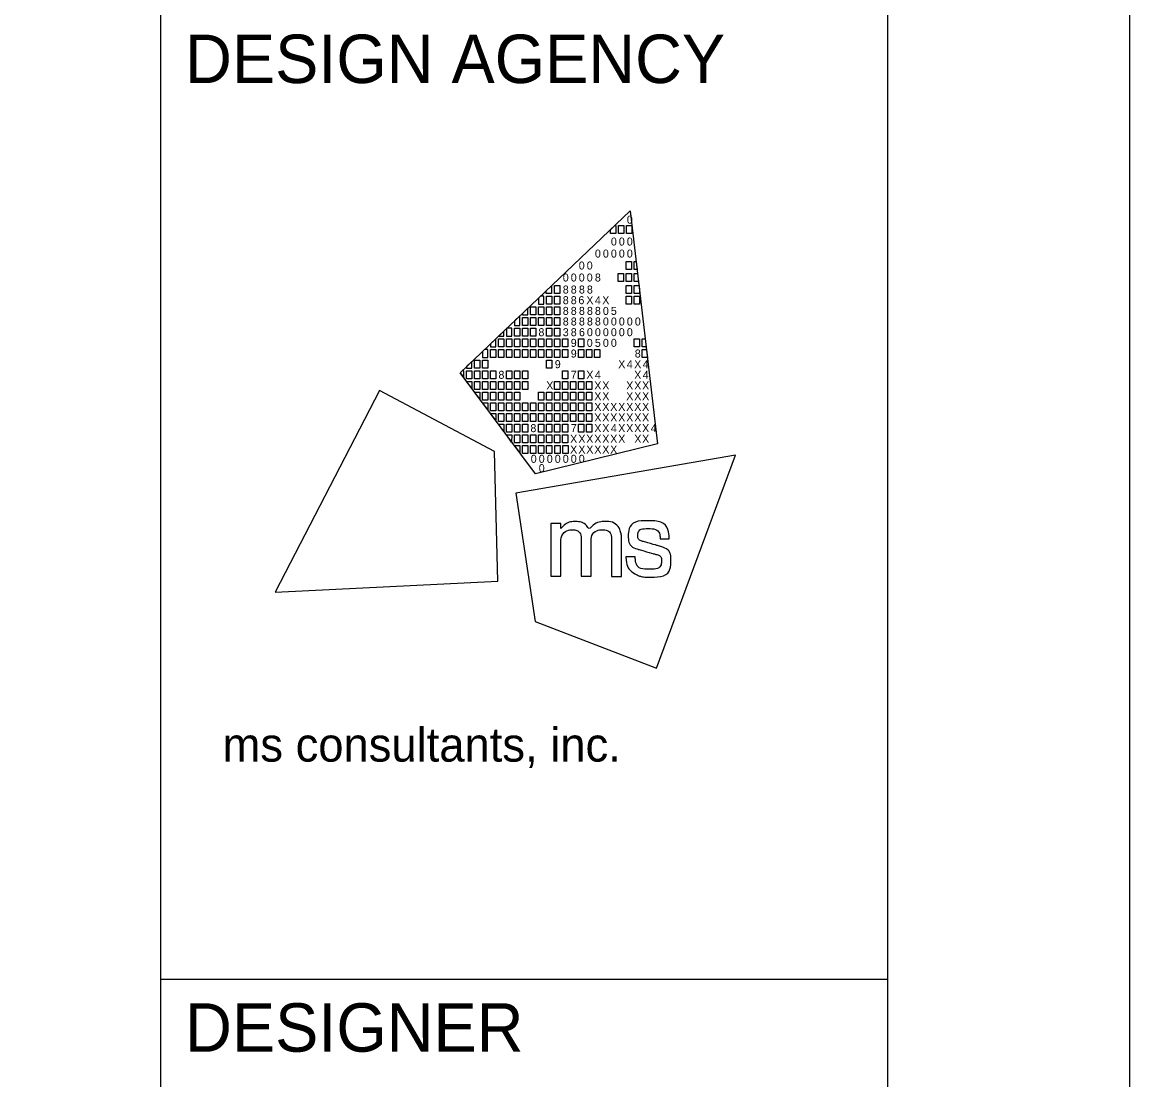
# Model space of a CAD drawing. Extents: x -2.6 to 34, y 0 to 22.
# Drawn here: x 31.714 to 34, y 2.292 to 4.476 of the extents above; entities that cross this region are included whole.
import ezdxf

# ---------------------------------------------------------------- set-up
doc = ezdxf.new("R2010")
doc.units = 0
for name, color, linetype in [('Default', 7, 'Continuous'), ('SH_Border', 7, 'Continuous'), ('SH_Cut_Line', 7, 'Continuous'), ('SH_Data', 7, 'Continuous')]:
    doc.layers.add(name, color=color, linetype=linetype)

msp = doc.modelspace()

# ---------------------------------------------------------------- linework, layer by layer
at = {"layer": 'Default'}
for p, q in [((32.6175, 3.7519), (32.9688, 4.0861)), ((32.9688, 4.0861), (32.9688, 4.0861)), ((32.9688, 4.0861), (33.0253, 3.6052)), ((32.773, 3.543), (32.6175, 3.7519)), ((33.0253, 3.6052), (32.773, 3.543))]:
    msp.add_line(p, q, dxfattribs=at)
for points in [[(32.9279, 4.0472), (32.9369, 4.0558), (32.9389, 4.0558), (32.9389, 4.0393), (32.9279, 4.0393)], [(32.9444, 4.0558), (32.9554, 4.0558), (32.9554, 4.0393), (32.9444, 4.0393)], [(32.9609, 4.0558), (32.9719, 4.0558), (32.9719, 4.0393), (32.9609, 4.0393)], [(32.9606, 3.9815), (32.9716, 3.9815), (32.9716, 3.965), (32.9606, 3.965)], [(32.9771, 3.9815), (32.9811, 3.9815), (32.983, 3.965), (32.9771, 3.965)], [(32.9441, 3.9567), (32.9551, 3.9567), (32.9551, 3.9402), (32.9441, 3.9402)], [(32.9606, 3.9567), (32.9716, 3.9567), (32.9716, 3.9402), (32.9606, 3.9402)], [(32.9771, 3.9567), (32.984, 3.9567), (32.9859, 3.9402), (32.9771, 3.9402)], [(32.7953, 3.9211), (32.8064, 3.9316), (32.8064, 3.9154), (32.7953, 3.9154)], [(32.7958, 3.9099), (32.8068, 3.9099), (32.8068, 3.8934), (32.7958, 3.8934)], [(32.8123, 3.9319), (32.8233, 3.9319), (32.8233, 3.9154), (32.8123, 3.9154)], [(32.8123, 3.9099), (32.8233, 3.9099), (32.8233, 3.8934), (32.8123, 3.8934)], [(32.9606, 3.9319), (32.9716, 3.9319), (32.9716, 3.9154), (32.9606, 3.9154)], [(32.9606, 3.9099), (32.9716, 3.9099), (32.9716, 3.8934), (32.9606, 3.8934)], [(32.9771, 3.9319), (32.9869, 3.9319), (32.9881, 3.9218), (32.9881, 3.9154), (32.9771, 3.9154)], [(32.9771, 3.9099), (32.9881, 3.9099), (32.9881, 3.8934), (32.9771, 3.8934)], [(32.7627, 3.8879), (32.7737, 3.8879), (32.7737, 3.8714), (32.7627, 3.8714)], [(32.7793, 3.8879), (32.7903, 3.8879), (32.7903, 3.8714), (32.7793, 3.8714)], [(32.7958, 3.8879), (32.8068, 3.8879), (32.8068, 3.8714), (32.7958, 3.8714)], [(32.8123, 3.8879), (32.8233, 3.8879), (32.8233, 3.8714), (32.8123, 3.8714)], [(32.7462, 3.8659), (32.7572, 3.8659), (32.7572, 3.8494), (32.7462, 3.8494)], [(32.7627, 3.8659), (32.7737, 3.8659), (32.7737, 3.8494), (32.7627, 3.8494)], [(32.7793, 3.8659), (32.7903, 3.8659), (32.7903, 3.8494), (32.7793, 3.8494)], [(32.7958, 3.8659), (32.8068, 3.8659), (32.8068, 3.8494), (32.7958, 3.8494)], [(32.8123, 3.8659), (32.8233, 3.8659), (32.8233, 3.8494), (32.8123, 3.8494)], [(32.7297, 3.8439), (32.7407, 3.8439), (32.7407, 3.8273), (32.7297, 3.8273)], [(32.7462, 3.8439), (32.7572, 3.8439), (32.7572, 3.8273), (32.7462, 3.8273)], [(32.7627, 3.8439), (32.7737, 3.8439), (32.7737, 3.8273), (32.7627, 3.8273)], [(32.7958, 3.8439), (32.8068, 3.8439), (32.8068, 3.8273), (32.7958, 3.8273)], [(32.8123, 3.8439), (32.8233, 3.8439), (32.8233, 3.8273), (32.8123, 3.8273)], [(32.6967, 3.8218), (32.7077, 3.8218), (32.7077, 3.8053), (32.6967, 3.8053)], [(32.7132, 3.8218), (32.7242, 3.8218), (32.7242, 3.8053), (32.7132, 3.8053)], [(32.7297, 3.8218), (32.7407, 3.8218), (32.7407, 3.8053), (32.7297, 3.8053)], [(32.7462, 3.8218), (32.7572, 3.8218), (32.7572, 3.8053), (32.7462, 3.8053)], [(32.7627, 3.8218), (32.7737, 3.8218), (32.7737, 3.8053), (32.7627, 3.8053)], [(32.7793, 3.8218), (32.7903, 3.8218), (32.7903, 3.8053), (32.7793, 3.8053)], [(32.7958, 3.8218), (32.8068, 3.8218), (32.8068, 3.8053), (32.7958, 3.8053)], [(32.8123, 3.8218), (32.8233, 3.8218), (32.8233, 3.8053), (32.8123, 3.8053)], [(32.8288, 3.8218), (32.8398, 3.8218), (32.8398, 3.8053), (32.8288, 3.8053)], [(32.8618, 3.8218), (32.8728, 3.8218), (32.8728, 3.8053), (32.8618, 3.8053)], [(32.9771, 3.8218), (32.9881, 3.8218), (32.9881, 3.8053), (32.9771, 3.8053)], [(32.9935, 3.8218), (32.9998, 3.8218), (33.0018, 3.8053), (32.9935, 3.8053)], [(32.6802, 3.7998), (32.6912, 3.7998), (32.6912, 3.7833), (32.6802, 3.7833)], [(32.6967, 3.7998), (32.7077, 3.7998), (32.7077, 3.7833), (32.6967, 3.7833)], [(32.7132, 3.7998), (32.7242, 3.7998), (32.7242, 3.7833), (32.7132, 3.7833)], [(32.7297, 3.7998), (32.7407, 3.7998), (32.7407, 3.7833), (32.7297, 3.7833)], [(32.7462, 3.7998), (32.7572, 3.7998), (32.7572, 3.7833), (32.7462, 3.7833)], [(32.7627, 3.7998), (32.7737, 3.7998), (32.7737, 3.7833), (32.7627, 3.7833)], [(32.7793, 3.7998), (32.7903, 3.7998), (32.7903, 3.7833), (32.7793, 3.7833)], [(32.7958, 3.7998), (32.8068, 3.7998), (32.8068, 3.7833), (32.7958, 3.7833)], [(32.8123, 3.7998), (32.8233, 3.7998), (32.8233, 3.7833), (32.8123, 3.7833)], [(32.8288, 3.7998), (32.8398, 3.7998), (32.8398, 3.7833), (32.8288, 3.7833)], [(32.8618, 3.7998), (32.8728, 3.7998), (32.8728, 3.7833), (32.8618, 3.7833)], [(32.8783, 3.7998), (32.8893, 3.7998), (32.8893, 3.7833), (32.8783, 3.7833)], [(32.8947, 3.7998), (32.9057, 3.7998), (32.9057, 3.7833), (32.8947, 3.7833)], [(32.9935, 3.7998), (33.0024, 3.7998), (33.0044, 3.7833), (32.9935, 3.7833)], [(32.6471, 3.7778), (32.6581, 3.7778), (32.6581, 3.7613), (32.6471, 3.7613)], [(32.6637, 3.7778), (32.6747, 3.7778), (32.6747, 3.7613), (32.6637, 3.7613)], [(32.7958, 3.7778), (32.8068, 3.7778), (32.8068, 3.7613), (32.7958, 3.7613)], [(32.6306, 3.7558), (32.6416, 3.7558), (32.6416, 3.7393), (32.6306, 3.7393)], [(32.6471, 3.7558), (32.6581, 3.7558), (32.6581, 3.7393), (32.6471, 3.7393)], [(32.6637, 3.7558), (32.6747, 3.7558), (32.6747, 3.7393), (32.6637, 3.7393)], [(32.6802, 3.7558), (32.6912, 3.7558), (32.6912, 3.7393), (32.6802, 3.7393)], [(32.7132, 3.7558), (32.7242, 3.7558), (32.7242, 3.7393), (32.7132, 3.7393)], [(32.7297, 3.7558), (32.7407, 3.7558), (32.7407, 3.7393), (32.7297, 3.7393)], [(32.7462, 3.7558), (32.7572, 3.7558), (32.7572, 3.7393), (32.7462, 3.7393)], [(32.8288, 3.7558), (32.8398, 3.7558), (32.8398, 3.7393), (32.8288, 3.7393)], [(32.8618, 3.7558), (32.8728, 3.7558), (32.8728, 3.7393), (32.8618, 3.7393)], [(32.6306, 3.7338), (32.6416, 3.7338), (32.6416, 3.72)], [(32.6471, 3.7338), (32.6581, 3.7338), (32.6581, 3.7173), (32.6471, 3.7173)], [(32.6637, 3.7338), (32.6747, 3.7338), (32.6747, 3.7173), (32.6637, 3.7173)], [(32.6802, 3.7338), (32.6912, 3.7338), (32.6912, 3.7173), (32.6802, 3.7173)], [(32.6967, 3.7338), (32.7077, 3.7338), (32.7077, 3.7173), (32.6967, 3.7173)], [(32.7132, 3.7338), (32.7242, 3.7338), (32.7242, 3.7173), (32.7132, 3.7173)], [(32.7297, 3.7338), (32.7407, 3.7338), (32.7407, 3.7173), (32.7297, 3.7173)], [(32.7462, 3.7338), (32.7572, 3.7338), (32.7572, 3.7173), (32.7462, 3.7173)], [(32.8123, 3.7338), (32.8233, 3.7338), (32.8233, 3.7173), (32.8123, 3.7173)], [(32.8288, 3.7338), (32.8398, 3.7338), (32.8398, 3.7173), (32.8288, 3.7173)], [(32.8453, 3.7338), (32.8563, 3.7338), (32.8563, 3.7173), (32.8453, 3.7173)], [(32.8618, 3.7338), (32.8728, 3.7338), (32.8728, 3.7173), (32.8618, 3.7173)], [(32.8783, 3.7338), (32.8893, 3.7338), (32.8893, 3.7173), (32.8783, 3.7173)], [(32.6471, 3.7117), (32.6581, 3.7117), (32.6581, 3.698)], [(32.6637, 3.7117), (32.6747, 3.7117), (32.6747, 3.6952), (32.6637, 3.6952)], [(32.6802, 3.7117), (32.6912, 3.7117), (32.6912, 3.6952), (32.6802, 3.6952)], [(32.6967, 3.7117), (32.7077, 3.7117), (32.7077, 3.6952), (32.6967, 3.6952)], [(32.7132, 3.7117), (32.7242, 3.7117), (32.7242, 3.6952), (32.7132, 3.6952)], [(32.7297, 3.7117), (32.7407, 3.7117), (32.7407, 3.6952), (32.7297, 3.6952)], [(32.7793, 3.7117), (32.7903, 3.7117), (32.7903, 3.6952), (32.7793, 3.6952)], [(32.7958, 3.7117), (32.8068, 3.7117), (32.8068, 3.6952), (32.7958, 3.6952)], [(32.8123, 3.7117), (32.8233, 3.7117), (32.8233, 3.6952), (32.8123, 3.6952)], [(32.8288, 3.7117), (32.8398, 3.7117), (32.8398, 3.6952), (32.8288, 3.6952)], [(32.8453, 3.7117), (32.8563, 3.7117), (32.8563, 3.6952), (32.8453, 3.6952)], [(32.8618, 3.7117), (32.8728, 3.7117), (32.8728, 3.6952), (32.8618, 3.6952)], [(32.8783, 3.7117), (32.8893, 3.7117), (32.8893, 3.6952), (32.8783, 3.6952)], [(32.6637, 3.6897), (32.6747, 3.6897), (32.6747, 3.676)], [(32.6747, 3.6897), (32.6747, 3.6897), (32.6747, 3.6897)], [(32.6802, 3.6897), (32.6912, 3.6897), (32.6912, 3.6732), (32.6802, 3.6732)], [(32.6967, 3.6897), (32.7077, 3.6897), (32.7077, 3.6732), (32.6967, 3.6732)], [(32.7132, 3.6897), (32.7242, 3.6897), (32.7242, 3.6732), (32.7132, 3.6732)], [(32.7297, 3.6897), (32.7407, 3.6897), (32.7407, 3.6732), (32.7297, 3.6732)], [(32.7462, 3.6897), (32.7572, 3.6897), (32.7572, 3.6732), (32.7462, 3.6732)], [(32.7627, 3.6897), (32.7737, 3.6897), (32.7737, 3.6732), (32.7627, 3.6732)], [(32.7793, 3.6897), (32.7903, 3.6897), (32.7903, 3.6732), (32.7793, 3.6732)], [(32.7958, 3.6897), (32.8068, 3.6897), (32.8068, 3.6732), (32.7958, 3.6732)], [(32.8123, 3.6897), (32.8233, 3.6897), (32.8233, 3.6732), (32.8123, 3.6732)], [(32.8288, 3.6897), (32.8398, 3.6897), (32.8398, 3.6732), (32.8288, 3.6732)], [(32.8453, 3.6897), (32.8563, 3.6897), (32.8563, 3.6732), (32.8453, 3.6732)], [(32.8618, 3.6897), (32.8728, 3.6897), (32.8728, 3.6732), (32.8618, 3.6732)], [(32.8783, 3.6897), (32.8893, 3.6897), (32.8893, 3.6732), (32.8783, 3.6732)], [(32.6802, 3.6677), (32.6912, 3.6677), (32.6912, 3.654)], [(32.6967, 3.6677), (32.7077, 3.6677), (32.7077, 3.6512), (32.6967, 3.6512)], [(32.7132, 3.6677), (32.7242, 3.6677), (32.7242, 3.6512), (32.7132, 3.6512)], [(32.7297, 3.6677), (32.7407, 3.6677), (32.7407, 3.6512), (32.7297, 3.6512)], [(32.7462, 3.6677), (32.7572, 3.6677), (32.7572, 3.6512), (32.7462, 3.6512)], [(32.7627, 3.6677), (32.7737, 3.6677), (32.7737, 3.6512), (32.7627, 3.6512)], [(32.7793, 3.6677), (32.7903, 3.6677), (32.7903, 3.6512), (32.7793, 3.6512)], [(32.7958, 3.6677), (32.8068, 3.6677), (32.8068, 3.6512), (32.7958, 3.6512)], [(32.8123, 3.6677), (32.8233, 3.6677), (32.8233, 3.6512), (32.8123, 3.6512)], [(32.8288, 3.6677), (32.8398, 3.6677), (32.8398, 3.6512), (32.8288, 3.6512)], [(32.8453, 3.6677), (32.8563, 3.6677), (32.8563, 3.6512), (32.8453, 3.6512)], [(32.8618, 3.6677), (32.8728, 3.6677), (32.8728, 3.6512), (32.8618, 3.6512)], [(32.8783, 3.6677), (32.8893, 3.6677), (32.8893, 3.6512), (32.8783, 3.6512)], [(32.7077, 3.6305), (32.6965, 3.6457), (32.7077, 3.6457)], [(32.7132, 3.6457), (32.7242, 3.6457), (32.7242, 3.6292), (32.7132, 3.6292)], [(32.7297, 3.6457), (32.7407, 3.6457), (32.7407, 3.6292), (32.7297, 3.6292)], [(32.7462, 3.6457), (32.7572, 3.6457), (32.7572, 3.6292), (32.7462, 3.6292)], [(32.7793, 3.6457), (32.7903, 3.6457), (32.7903, 3.6292), (32.7793, 3.6292)], [(32.7958, 3.6457), (32.8068, 3.6457), (32.8068, 3.6292), (32.7958, 3.6292)], [(32.8123, 3.6457), (32.8233, 3.6457), (32.8233, 3.6292), (32.8123, 3.6292)], [(32.8288, 3.6457), (32.8398, 3.6457), (32.8398, 3.6292), (32.8288, 3.6292)], [(32.8618, 3.6457), (32.8728, 3.6457), (32.8728, 3.6292), (32.8618, 3.6292)], [(32.8783, 3.6457), (32.8893, 3.6457), (32.8893, 3.6292), (32.8783, 3.6292)], [(32.724, 3.6082), (32.7132, 3.6237), (32.7242, 3.6237)], [(32.7297, 3.6237), (32.7407, 3.6237), (32.7407, 3.6072), (32.7297, 3.6072)], [(32.7462, 3.6237), (32.7572, 3.6237), (32.7572, 3.6072), (32.7462, 3.6072)], [(32.7627, 3.6237), (32.7737, 3.6237), (32.7737, 3.6072), (32.7627, 3.6072)], [(32.7793, 3.6237), (32.7903, 3.6237), (32.7903, 3.6072), (32.7793, 3.6072)], [(32.7958, 3.6237), (32.8068, 3.6237), (32.8068, 3.6072), (32.7958, 3.6072)], [(32.8123, 3.6237), (32.8233, 3.6237), (32.8233, 3.6072), (32.8123, 3.6072)], [(32.8288, 3.6237), (32.8398, 3.6237), (32.8398, 3.6072), (32.8288, 3.6072)], [(32.7302, 3.6017), (32.7407, 3.6017), (32.7408, 3.5875)], [(32.7463, 3.6017), (32.7573, 3.6017), (32.7573, 3.5852), (32.7463, 3.5852)], [(32.763, 3.6017), (32.774, 3.6017), (32.774, 3.5852), (32.763, 3.5852)], [(32.7794, 3.6017), (32.7904, 3.6017), (32.7904, 3.5852), (32.7794, 3.5852)], [(32.796, 3.6017), (32.807, 3.6017), (32.807, 3.5852), (32.796, 3.5852)], [(32.8129, 3.6017), (32.8239, 3.6017), (32.8239, 3.5851), (32.8129, 3.5851)], [(32.8296, 3.6017), (32.8406, 3.6017), (32.8406, 3.5851), (32.8296, 3.5851)]]:
    msp.add_lwpolyline(points, close=True, dxfattribs=at)
for points in [[(32.7903, 3.9099), (32.7836, 3.9099), (32.7793, 3.9058), (32.7793, 3.8934), (32.7903, 3.8934), (32.7903, 3.9099)], [(32.7407, 3.8691), (32.7297, 3.8587), (32.7297, 3.8494), (32.7407, 3.8494), (32.7407, 3.8691)], [(32.7572, 3.8849), (32.7462, 3.8744), (32.7462, 3.8714), (32.7572, 3.8714), (32.7572, 3.8849)], [(32.7242, 3.8439), (32.7141, 3.8439), (32.7132, 3.843), (32.7132, 3.8273), (32.7242, 3.8273), (32.7242, 3.8439)], [(32.6912, 3.822), (32.6802, 3.8115), (32.6802, 3.8053), (32.6912, 3.8053), (32.6912, 3.822)], [(32.7077, 3.8377), (32.6968, 3.8273), (32.7077, 3.8273), (32.7077, 3.8377)], [(32.6747, 3.7998), (32.6679, 3.7998), (32.6637, 3.7958), (32.6637, 3.7833), (32.6747, 3.7833), (32.6747, 3.7998)], [(32.6416, 3.7749), (32.6306, 3.7644), (32.6306, 3.7613), (32.6416, 3.7613), (32.6416, 3.7749)], [(32.6251, 3.7558), (32.6216, 3.7558), (32.6175, 3.7519), (32.6251, 3.7417), (32.6251, 3.7558)], [(32.4512, 3.7149), (32.2359, 3.2988), (32.6956, 3.3215), (32.6884, 3.5892), (32.4512, 3.7149)], [(33.0229, 3.1422), (33.1859, 3.5814), (32.7324, 3.5029), (32.7722, 3.2381), (33.0229, 3.1422)]]:
    msp.add_lwpolyline(points, dxfattribs=at)
for points in [[(32.8048, 3.3315), (32.8048, 3.3315), (32.8048, 3.4409), (32.8048, 3.4409), (32.8048, 3.4409), (32.8255, 3.4409), (32.8255, 3.4409), (32.8255, 3.4409), (32.8255, 3.4297), (32.8255, 3.4297), (32.8346, 3.4399), (32.8457, 3.4445), (32.8555, 3.4445), (32.8688, 3.4445), (32.8791, 3.4372), (32.8837, 3.4266), (32.8915, 3.4381), (32.905, 3.4446), (32.9166, 3.4446), (32.9325, 3.4446), (32.9451, 3.435), (32.9494, 3.4213), (32.9494, 3.4212), (32.9494, 3.4212), (32.9494, 3.4212), (32.9501, 3.419), (32.9506, 3.4172), (32.9506, 3.4071), (32.9506, 3.4071), (32.9506, 3.3314), (32.9506, 3.3314), (32.9506, 3.3314), (32.9303, 3.3314), (32.9303, 3.3314), (32.9303, 3.3314), (32.9303, 3.4048), (32.9303, 3.4048), (32.9303, 3.4201), (32.9219, 3.4274), (32.911, 3.4274), (32.8995, 3.4274), (32.8879, 3.4171), (32.8879, 3.4001), (32.8879, 3.4001), (32.8879, 3.3315), (32.8879, 3.3315), (32.8879, 3.3315), (32.8674, 3.3315), (32.8674, 3.3315), (32.8674, 3.3315), (32.8674, 3.4059), (32.8674, 3.4059), (32.8674, 3.4203), (32.8588, 3.4274), (32.8496, 3.4274), (32.8384, 3.4274), (32.8254, 3.417), (32.8254, 3.3962), (32.8254, 3.3962), (32.8254, 3.3315), (32.8254, 3.3315), (32.8254, 3.3315), (32.8048, 3.3315), (32.8048, 3.3315)], [(32.9595, 3.3709), (32.9595, 3.3709), (32.9595, 3.3717), (32.9595, 3.3717), (32.9595, 3.3717), (32.9603, 3.3717), (32.9603, 3.3717), (32.9603, 3.3717), (32.9783, 3.3717), (32.9783, 3.3717), (32.9783, 3.3717), (32.9789, 3.3717), (32.9789, 3.3717), (32.9789, 3.3717), (32.979, 3.371), (32.979, 3.371), (32.9803, 3.3554), (32.9887, 3.346), (33.009, 3.346), (33.0273, 3.346), (33.0333, 3.3554), (33.0333, 3.3631), (33.0333, 3.3732), (33.0256, 3.3758), (33.0175, 3.378), (33.0175, 3.378), (32.987, 3.3867), (32.987, 3.3867), (32.972, 3.3909), (32.9648, 3.4019), (32.9648, 3.4142), (32.9648, 3.4303), (32.9768, 3.4462), (33.0052, 3.4462), (33.0348, 3.4462), (33.0489, 3.4285), (33.0489, 3.4095), (33.0489, 3.4095), (33.0489, 3.4087), (33.0489, 3.4087), (33.0489, 3.4087), (33.0482, 3.4087), (33.0482, 3.4087), (33.0482, 3.4087), (33.0312, 3.4087), (33.0312, 3.4087), (33.0312, 3.4087), (33.0305, 3.4087), (33.0305, 3.4087), (33.0305, 3.4087), (33.0305, 3.4094), (33.0305, 3.4094), (33.0301, 3.4208), (33.0226, 3.43), (33.0056, 3.43), (32.9891, 3.43), (32.9843, 3.4218), (32.9843, 3.4157), (32.9843, 3.4108), (32.9869, 3.4059), (32.9959, 3.4033), (32.9959, 3.4033), (33.0255, 3.3948), (33.0255, 3.3948), (33.0462, 3.3889), (33.0527, 3.3777), (33.0527, 3.3639), (33.0527, 3.3462), (33.041, 3.3298), (33.0087, 3.3298), (32.9952, 3.3298), (32.9877, 3.3321), (32.9823, 3.3348), (32.969, 3.3414), (32.9609, 3.3536), (32.9595, 3.3709)]]:
    msp.add_open_spline(points, degree=3, dxfattribs=at)
at = {"layer": 'SH_Border'}
for p, q in [((32, 0.5), (32, 21.5)), ((32, 2.5), (33.5, 2.5))]:
    msp.add_line(p, q, dxfattribs=at)
msp.add_lwpolyline([(1.5, 21.5), (33.5, 21.5), (33.5, 0.5), (1.5, 0.5)], close=True, dxfattribs=at)
at = {"layer": 'SH_Cut_Line'}
msp.add_lwpolyline([(0, 0), (34, 0), (34, 22), (0, 22)], close=True, dxfattribs=at)
at = {"layer": 'SH_Data'}
msp.add_line((32.75, 3.5), (32.75, 3.5), dxfattribs=at)

# ---------------------------------------------------------------- texts
at = {"layer": 'Default'}
for s, p in [('0', (32.9617, 4.0597)), ('0', (32.9288, 4.0145)), ('0', (32.9452, 4.0145)), ('0', (32.9617, 4.0145)), ('0', (32.8958, 3.9897)), ('0', (32.9123, 3.9897)), ('0', (32.9288, 3.9897)), ('0', (32.9452, 3.9897)), ('0', (32.9617, 3.9897)), ('0', (32.8625, 3.965)), ('0', (32.879, 3.965)), ('0', (32.8295, 3.9402)), ('0', (32.846, 3.9402)), ('0', (32.8625, 3.9402)), ('0', (32.879, 3.9402)), ('8', (32.8958, 3.9402)), ('8', (32.8295, 3.9154)), ('8', (32.8295, 3.8934)), ('8', (32.846, 3.9154)), ('8', (32.846, 3.8934)), ('6', (32.8618, 3.8934)), ('8', (32.8628, 3.9154)), ('X', (32.8781, 3.8934)), ('8', (32.8793, 3.9154)), ('4', (32.8958, 3.8934)), ('X', (32.911, 3.8934)), ('8', (32.8295, 3.8713)), ('8', (32.846, 3.8713)), ('8', (32.8628, 3.8713)), ('8', (32.8794, 3.8713)), ('8', (32.8958, 3.8713)), ('0', (32.9123, 3.8713)), ('5', (32.9287, 3.8713)), ('8', (32.8295, 3.8494)), ('8', (32.846, 3.8494)), ('8', (32.8628, 3.8494)), ('8', (32.8794, 3.8494)), ('8', (32.8958, 3.8494)), ('0', (32.9123, 3.8494)), ('0', (32.9288, 3.8494)), ('0', (32.9452, 3.8494)), ('0', (32.9617, 3.8494)), ('0', (32.9782, 3.8494)), ('8', (32.7793, 3.8273)), ('3', (32.8295, 3.8273)), ('8', (32.846, 3.8273)), ('6', (32.8629, 3.8273)), ('0', (32.8793, 3.8273)), ('0', (32.8958, 3.8273)), ('0', (32.9123, 3.8273)), ('0', (32.9288, 3.8273)), ('0', (32.9452, 3.8273)), ('0', (32.9617, 3.8273)), ('9', (32.846, 3.8053)), ('0', (32.879, 3.8053)), ('5', (32.8957, 3.8053)), ('0', (32.9123, 3.8053)), ('0', (32.9288, 3.8053)), ('9', (32.846, 3.7833)), ('8', (32.9781, 3.7833)), ('9', (32.813, 3.7613)), ('X', (32.9439, 3.7613)), ('4', (32.9617, 3.7613)), ('X', (32.9769, 3.7613)), ('4', (32.9946, 3.7613)), ('8', (32.6967, 3.7393)), ('7', (32.846, 3.7393)), ('X', (32.8781, 3.7393)), ('4', (32.8958, 3.7393)), ('X', (32.9769, 3.7393)), ('4', (32.9946, 3.7393)), ('X', (32.7955, 3.7173)), ('X', (32.8945, 3.7173)), ('X', (32.911, 3.7173)), ('X', (32.9604, 3.7173)), ('X', (32.9769, 3.7173)), ('X', (32.9933, 3.7173)), ('X', (32.8945, 3.6952)), ('X', (32.911, 3.6952)), ('X', (32.9604, 3.6952)), ('X', (32.9769, 3.6952)), ('X', (32.9933, 3.6952)), ('X', (32.8945, 3.6732)), ('X', (32.911, 3.6732)), ('X', (32.9274, 3.6732)), ('X', (32.9439, 3.6732)), ('X', (32.9604, 3.6732)), ('X', (32.9769, 3.6732)), ('X', (32.9933, 3.6732)), ('X', (32.8945, 3.6512)), ('X', (32.911, 3.6512)), ('X', (32.9274, 3.6512)), ('X', (32.9439, 3.6512)), ('X', (32.9604, 3.6512)), ('X', (32.9769, 3.6512)), ('X', (32.9933, 3.6512)), ('8', (32.7627, 3.6292)), ('7', (32.846, 3.6292)), ('X', (32.8945, 3.6292)), ('X', (32.911, 3.6292)), ('4', (32.9288, 3.6292)), ('X', (32.9439, 3.6292)), ('X', (32.9604, 3.6292)), ('X', (32.9769, 3.6292)), ('X', (32.9933, 3.6292)), ('4', (33.0111, 3.6292)), ('X', (32.8447, 3.6072)), ('X', (32.8616, 3.6072)), ('X', (32.878, 3.6072)), ('X', (32.8945, 3.6072)), ('X', (32.911, 3.6072)), ('X', (32.9274, 3.6072)), ('X', (32.9439, 3.6072)), ('X', (32.9771, 3.6072)), ('X', (32.9933, 3.6072)), ('X', (32.8447, 3.5851)), ('X', (32.8616, 3.5851)), ('X', (32.878, 3.5851)), ('X', (32.8945, 3.5851)), ('X', (32.911, 3.5851)), ('X', (32.9274, 3.5851)), ('0', (32.7634, 3.5659)), ('0', (32.7799, 3.5659)), ('0', (32.7965, 3.5659)), ('0', (32.813, 3.5659)), ('0', (32.8295, 3.5659)), ('0', (32.846, 3.5659)), ('0', (32.8625, 3.5659)), ('0', (32.7799, 3.5467))]:
    msp.add_text(s, height=0.0165, rotation=360, dxfattribs=at).set_placement(p)
at = {"layer": 'SH_Border'}
msp.add_text('ms consultants, inc.', height=0.07, rotation=360, dxfattribs=at).set_placement((32.1273, 2.9489))
at = {"layer": 'SH_Data'}
for s, p in [('DESIGN AGENCY', (32.05, 4.35)), ('DESIGNER', (32.05, 2.35))]:
    msp.add_text(s, height=0.1, dxfattribs=at).set_placement(p)

doc.saveas('drawing.dxf')
